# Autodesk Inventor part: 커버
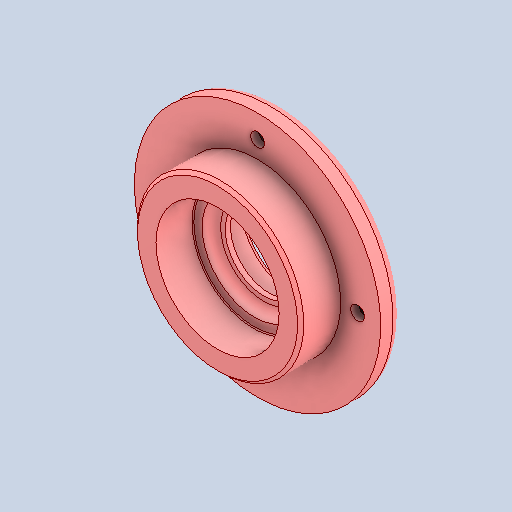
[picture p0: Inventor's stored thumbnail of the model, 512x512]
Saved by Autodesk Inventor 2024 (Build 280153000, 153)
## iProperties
Created: 2026-07
Part Number: 커버
Material: 알루미늄 6061
Document SubType Name: Modeling
Designer: com
Density: 2.7 g/cm^3
Appearance: 기본값
Company: 한국ATC센터
Author: jhkim
Revision Number: 1
Sending System: Autodesk Inventor 2027
Preprocessor: ST-DEVELOPER v20.1
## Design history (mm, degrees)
node "커버1"
node "솔리드2"
node "솔리드1"
